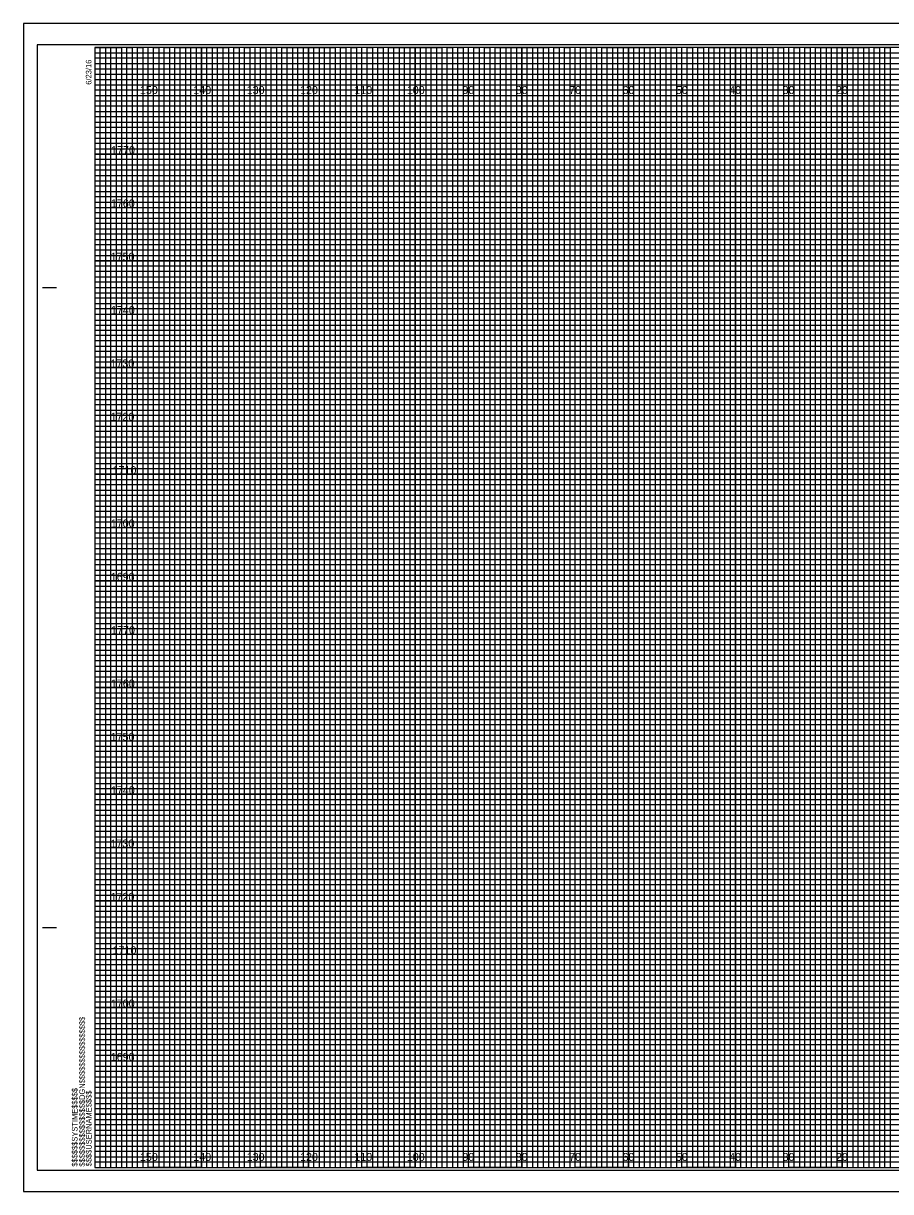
# Model space of a CAD drawing. Extents: x -13 to 1780, y -15 to 3284.
# Drawn here: x 1443.3 to 1605.8, y -14.8 to 204.2 of the extents above; entities that cross this region are included whole.
import ezdxf

# ---------------------------------------------------------------- set-up
doc = ezdxf.new("R2010")
doc.units = 0
for name, color, linetype in [('Prop Retaining Wall', 7, 'Continuous'), ('Prop SS Cut Line', 7, 'Continuous'), ('Prop SS Fill Line', 7, 'Continuous'), ('Prop SS Transition Line', 7, 'Continuous'), ('Prop XS Earthwork Shape', 7, 'Continuous'), ('Prop XS Noise Wall', 7, 'Continuous'), ('Prop XS Station Labels', 7, 'Continuous'), ('Raster_Level_0', 7, 'Continuous'), ('Scratch_Level_3', 7, 'Continuous'), ('Scratch_Level_7', 7, 'Continuous'), ('Typical Bridge Rail CELL', 7, 'Continuous')]:
    doc.layers.add(name, color=color, linetype=linetype)

msp = doc.modelspace()

# ---------------------------------------------------------------- linework, layer by layer
at = {"layer": 'Prop Retaining Wall'}
for p, q in [((1446.88, 154.71), (1449.38, 154.71)), ((1446.98, 154.71), (1449.48, 154.71)), ((1446.88, 34.71), (1449.38, 34.71)), ((1446.98, 34.71), (1449.48, 34.71)), ((1456.68, -10.29), (1456.68, -10.29)), ((1456.68, -10.29), (1456.68, -10.29)), ((1456.68, -10.29), (1456.68, -10.29)), ((1456.68, -10.29), (1456.68, -10.29)), ((1456.68, -10.29), (1456.68, -10.29)), ((1456.68, -10.29), (1456.68, -10.29)), ((1456.68, -10.29), (1456.68, -10.29))]:
    msp.add_line(p, q, dxfattribs=at)
msp.add_lwpolyline([(1776.68, 199.71), (1456.68, 199.71), (1456.68, -10.29), (1776.68, -10.29)], close=True, dxfattribs=at)
at = {"layer": 'Prop SS Cut Line'}
for points in [[(1456.68, 199.71), (1461.68, 199.71), (1461.68, -10.29), (1471.68, -10.29), (1471.68, 199.71), (1481.68, 199.71), (1481.68, -10.29), (1491.68, -10.29), (1491.68, 199.71), (1501.68, 199.71), (1501.68, -10.29), (1511.68, -10.29), (1511.68, 199.71), (1521.68, 199.71), (1521.68, -10.29), (1531.68, -10.29), (1531.68, 199.71), (1541.68, 199.71), (1541.68, -10.29), (1551.68, -10.29), (1551.68, 199.71), (1561.68, 199.71), (1561.68, -10.29), (1571.68, -10.29), (1571.68, 199.71), (1581.68, 199.71), (1581.68, -10.29), (1591.68, -10.29), (1591.68, 199.71), (1601.68, 199.71), (1601.68, -10.29), (1611.68, -10.29)], [(1456.68, 194.71), (1731.68, 194.71)], [(1456.68, 174.71), (1776.68, 174.71), (1776.68, 184.71), (1456.68, 184.71)], [(1456.68, 154.71), (1776.68, 154.71), (1776.68, 164.71), (1456.68, 164.71)], [(1456.68, 134.71), (1776.68, 134.71), (1776.68, 144.71), (1456.68, 144.71)], [(1456.68, 114.71), (1776.68, 114.71), (1776.68, 124.71), (1456.68, 124.71)], [(1456.68, 94.71), (1776.68, 94.71), (1776.68, 104.71), (1456.68, 104.71)], [(1456.68, 74.71), (1776.68, 74.71), (1776.68, 84.71), (1456.68, 84.71)], [(1456.68, 54.71), (1776.68, 54.71), (1776.68, 64.71), (1456.68, 64.71)], [(1456.68, 34.71), (1776.68, 34.71), (1776.68, 44.71), (1456.68, 44.71)], [(1456.68, 14.71), (1776.68, 14.71), (1776.68, 24.71), (1456.68, 24.71)], [(1456.68, -5.29), (1776.68, -5.29), (1776.68, 4.71), (1456.68, 4.71)]]:
    msp.add_lwpolyline(points, dxfattribs=at)
at = {"layer": 'Prop SS Fill Line'}
for p, q in [((1466.68, 199.71), (1456.68, 199.71)), ((1466.68, -10.29), (1466.68, 199.71)), ((1486.68, 199.71), (1476.68, 199.71)), ((1476.68, 199.71), (1476.68, -10.29)), ((1486.68, -10.29), (1486.68, 199.71)), ((1506.68, 199.71), (1496.68, 199.71)), ((1496.68, 199.71), (1496.68, -10.29)), ((1506.68, -10.29), (1506.68, 199.71)), ((1526.68, 199.71), (1516.68, 199.71)), ((1516.68, 199.71), (1516.68, -10.29)), ((1526.68, -10.29), (1526.68, 199.71)), ((1546.68, 199.71), (1536.68, 199.71)), ((1536.68, 199.71), (1536.68, -10.29)), ((1546.68, -10.29), (1546.68, 199.71)), ((1566.68, 199.71), (1556.68, 199.71)), ((1556.68, 199.71), (1556.68, -10.29)), ((1566.68, -10.29), (1566.68, 199.71)), ((1586.68, 199.71), (1576.68, 199.71)), ((1576.68, 199.71), (1576.68, -10.29)), ((1586.68, -10.29), (1586.68, 199.71)), ((1606.68, 199.71), (1596.68, 199.71)), ((1596.68, 199.71), (1596.68, -10.29)), ((1476.68, -10.29), (1466.68, -10.29)), ((1496.68, -10.29), (1486.68, -10.29)), ((1516.68, -10.29), (1506.68, -10.29)), ((1536.68, -10.29), (1526.68, -10.29)), ((1556.68, -10.29), (1546.68, -10.29)), ((1576.68, -10.29), (1566.68, -10.29)), ((1596.68, -10.29), (1586.68, -10.29))]:
    msp.add_line(p, q, dxfattribs=at)
for points in [[(1456.68, 189.71), (1776.68, 189.71), (1776.68, 179.71), (1456.68, 179.71)], [(1456.68, 169.71), (1776.68, 169.71), (1776.68, 159.71), (1456.68, 159.71)], [(1456.68, 149.71), (1776.68, 149.71), (1776.68, 139.71), (1456.68, 139.71)], [(1456.68, 129.71), (1776.68, 129.71), (1776.68, 119.71), (1456.68, 119.71)], [(1456.68, 109.71), (1776.68, 109.71), (1776.68, 99.71), (1456.68, 99.71)], [(1456.68, 89.71), (1776.68, 89.71), (1776.68, 79.71), (1456.68, 79.71)], [(1456.68, 69.71), (1776.68, 69.71), (1776.68, 59.71), (1456.68, 59.71)], [(1456.68, 49.71), (1776.68, 49.71), (1776.68, 39.71), (1456.68, 39.71)], [(1456.68, 29.71), (1776.68, 29.71), (1776.68, 19.71), (1456.68, 19.71)], [(1456.68, 9.71), (1776.68, 9.71), (1776.68, -0.29), (1456.68, -0.29)]]:
    msp.add_lwpolyline(points, dxfattribs=at)
at = {"layer": 'Prop SS Transition Line'}
for p, q in [((1456.68, 198.71), (1716.68, 198.71)), ((1716.68, 197.69), (1456.68, 197.69)), ((1456.68, 197.69), (1456.68, 196.71)), ((1456.68, 196.71), (1716.68, 196.71)), ((1716.68, 195.6), (1456.68, 195.6)), ((1456.68, 195.6), (1456.68, 193.71)), ((1456.68, 193.71), (1776.68, 193.71))]:
    msp.add_line(p, q, dxfattribs=at)
for points in [[(1456.68, 192.71), (1726.68, 192.71), (1776.68, 192.71), (1776.68, 191.71), (1456.68, 191.71)], [(1456.68, 190.71), (1776.68, 190.71), (1776.68, 188.71), (1456.68, 188.71)], [(1456.68, 187.71), (1776.68, 187.71), (1776.68, 186.71), (1456.68, 186.69)], [(1456.68, 185.71), (1776.68, 185.71), (1776.68, 183.71), (1456.68, 183.71)], [(1456.68, 182.71), (1776.68, 182.71), (1776.68, 181.71), (1456.68, 181.71)], [(1456.68, 180.71), (1776.68, 180.71), (1776.68, 178.71), (1456.68, 178.71)], [(1456.68, 177.71), (1776.68, 177.71), (1776.68, 176.71), (1456.68, 176.71)], [(1456.68, 175.71), (1776.68, 175.71), (1776.68, 173.71), (1456.68, 173.71)], [(1456.68, 172.71), (1776.68, 172.71), (1776.68, 171.71), (1456.68, 171.71)], [(1456.68, 170.71), (1776.68, 170.71), (1776.68, 168.71), (1456.68, 168.71)], [(1456.68, 167.71), (1776.68, 167.71), (1776.68, 166.71), (1456.68, 166.71)], [(1456.68, 165.71), (1776.68, 165.71), (1776.68, 163.66), (1776.68, 162.71), (1776.68, 161.71), (1456.68, 161.71)], [(1456.68, 163.71), (1776.68, 163.71), (1776.68, 162.71), (1456.68, 162.71)], [(1456.68, 160.71), (1776.68, 160.71), (1776.68, 158.71), (1456.68, 158.74)], [(1456.68, 158.74), (1776.68, 158.71), (1776.68, 157.71), (1456.68, 157.71)], [(1456.68, 156.71), (1776.68, 156.71), (1776.68, 155.71), (1456.68, 155.71)], [(1456.68, 153.71), (1776.68, 153.71), (1776.68, 152.71), (1456.68, 152.71)], [(1456.68, 151.71), (1776.68, 151.71), (1776.68, 150.71), (1456.68, 150.71)], [(1456.61, 148.6), (1776.68, 148.6), (1776.68, 147.59), (1456.61, 147.59)], [(1456.68, 146.71), (1776.68, 146.71), (1776.68, 145.71), (1456.68, 145.71)], [(1456.68, 143.71), (1776.68, 143.71), (1776.68, 142.71), (1456.68, 142.71)], [(1456.68, 141.71), (1776.68, 141.71), (1776.68, 140.71), (1456.68, 140.71)], [(1456.68, 138.71), (1776.68, 138.71), (1776.68, 137.71), (1456.68, 137.71)], [(1456.68, 136.71), (1776.68, 136.71), (1776.68, 135.71), (1456.68, 135.71)], [(1456.68, 133.71), (1776.68, 133.71), (1776.68, 132.71), (1456.68, 132.71)], [(1456.68, 131.71), (1776.68, 131.71), (1776.68, 130.71), (1456.68, 130.71)], [(1456.68, 128.71), (1776.68, 128.71), (1776.67, 127.69), (1456.68, 127.71)], [(1456.68, 126.71), (1776.68, 126.71), (1776.68, 125.71), (1456.68, 125.71)], [(1456.68, 123.71), (1776.68, 123.71), (1776.68, 122.71), (1456.68, 122.71)], [(1456.68, 121.71), (1776.68, 121.71), (1776.68, 120.71), (1456.68, 120.71)], [(1456.68, 118.71), (1776.68, 118.71), (1776.68, 117.71), (1456.68, 117.71)], [(1456.68, 116.71), (1776.68, 116.71), (1776.68, 115.71), (1456.68, 115.71)], [(1456.68, 113.71), (1776.68, 113.71), (1776.68, 112.71), (1456.68, 112.71)], [(1456.68, 111.71), (1776.68, 111.71), (1776.68, 110.71), (1456.68, 110.71)], [(1456.68, 108.71), (1776.68, 108.71), (1776.68, 107.71), (1456.68, 107.71)], [(1456.68, 106.7), (1776.75, 106.62), (1776.68, 105.71), (1456.68, 105.71)], [(1456.68, 103.71), (1776.68, 103.71), (1776.68, 102.71), (1456.68, 102.71)], [(1456.68, 101.71), (1776.68, 101.71), (1776.68, 100.71), (1456.68, 100.71)], [(1456.68, 98.71), (1776.68, 98.71), (1776.68, 97.71), (1456.68, 97.71)], [(1456.68, 96.71), (1776.68, 96.71), (1776.68, 95.71), (1456.68, 95.71)], [(1456.68, 93.71), (1776.68, 93.71), (1776.68, 92.71), (1456.68, 92.71)], [(1456.68, 91.71), (1776.68, 91.71), (1776.68, 90.71), (1456.68, 90.71)], [(1456.68, 88.71), (1776.68, 88.71), (1776.68, 87.71), (1456.68, 87.71)], [(1456.68, 86.71), (1776.68, 86.71), (1776.68, 85.71), (1456.68, 85.71)], [(1456.68, 83.71), (1776.68, 83.71), (1776.68, 82.71), (1456.68, 82.71)], [(1456.68, 81.71), (1776.68, 81.71), (1776.68, 80.71), (1456.68, 80.71)], [(1456.68, 78.71), (1776.68, 78.71), (1776.68, 77.71), (1456.68, 77.71)], [(1456.68, 76.71), (1776.68, 76.71), (1776.68, 75.71), (1456.68, 75.71)], [(1456.68, 73.71), (1776.68, 73.71), (1776.68, 72.71), (1456.68, 72.71)], [(1456.68, 71.71), (1776.68, 71.71), (1776.68, 70.71), (1456.68, 70.71)], [(1456.68, 68.71), (1776.68, 68.71), (1776.67, 67.69), (1456.68, 67.71)], [(1456.68, 66.71), (1776.68, 66.71), (1776.68, 65.71), (1456.68, 65.71)], [(1456.68, 63.71), (1776.68, 63.71), (1776.68, 62.71), (1456.68, 62.71)], [(1456.68, 61.71), (1776.68, 61.71), (1776.68, 60.71), (1456.68, 60.71)], [(1456.68, 58.71), (1776.68, 58.71), (1776.68, 57.71), (1456.68, 57.71)], [(1456.68, 56.71), (1776.68, 56.71), (1776.68, 55.71), (1456.68, 55.71)], [(1456.68, 53.71), (1776.68, 53.71), (1776.68, 52.71), (1456.68, 52.71)], [(1456.68, 51.71), (1776.68, 51.71), (1776.68, 50.71), (1456.68, 50.71)], [(1456.68, 48.71), (1776.68, 48.71), (1776.68, 47.71), (1456.68, 47.71)], [(1456.68, 46.7), (1776.75, 46.62), (1776.68, 45.71), (1456.68, 45.71)], [(1456.68, 43.71), (1776.68, 43.71), (1776.68, 42.71), (1456.68, 42.71)], [(1456.68, 41.71), (1776.68, 41.71), (1776.68, 40.71), (1456.68, 40.71)], [(1456.68, 38.71), (1776.68, 38.71), (1776.68, 37.71), (1456.68, 37.71)], [(1456.68, 36.71), (1776.68, 36.71), (1776.68, 35.71), (1456.68, 35.71)], [(1456.68, 33.71), (1776.68, 33.71), (1776.68, 32.71), (1456.68, 32.71)], [(1456.68, 31.71), (1776.68, 31.71), (1776.68, 30.71), (1456.68, 30.71)], [(1456.68, 28.71), (1776.68, 28.71), (1776.68, 27.71), (1456.68, 27.71)], [(1456.68, 26.71), (1776.68, 26.71), (1776.68, 25.71), (1456.68, 25.71)], [(1456.68, 23.71), (1776.68, 23.71), (1776.68, 22.71), (1456.68, 22.71)], [(1456.68, 21.71), (1776.68, 21.71), (1776.68, 20.71), (1456.68, 20.71)], [(1456.68, 18.71), (1776.68, 18.71), (1776.68, 17.71), (1456.68, 17.71)], [(1456.68, 16.71), (1776.68, 16.71), (1776.68, 15.71), (1456.68, 15.71)], [(1456.68, 13.71), (1776.68, 13.71), (1776.68, 12.71), (1456.68, 12.71)], [(1456.68, 11.71), (1776.68, 11.71), (1776.68, 10.71), (1456.68, 10.71)], [(1456.68, 8.71), (1776.68, 8.71), (1776.68, 7.71), (1456.68, 7.71)], [(1456.68, 6.71), (1776.68, 6.71), (1776.68, 5.71), (1456.68, 5.71)], [(1456.68, 3.71), (1776.68, 3.71), (1776.68, 2.71), (1456.68, 2.71)], [(1456.68, 1.71), (1776.68, 1.71), (1776.68, 0.71), (1456.68, 0.71)], [(1456.68, -1.29), (1776.68, -1.29), (1776.68, -2.29), (1456.68, -2.29)], [(1456.68, -3.29), (1776.68, -3.29), (1776.68, -4.29), (1456.68, -4.29)], [(1456.68, -6.29), (1776.68, -6.29), (1776.68, -7.29), (1456.68, -7.29)], [(1456.68, -8.29), (1776.68, -8.29), (1776.68, -9.29), (1456.68, -9.29)]]:
    msp.add_lwpolyline(points, dxfattribs=at)
at = {"layer": 'Prop XS Earthwork Shape'}
msp.add_lwpolyline([(1443.28, -14.79), (1779.98, -14.79), (1779.98, 204.21), (1443.28, 204.21)], close=True, dxfattribs=at)
at = {"layer": 'Prop XS Noise Wall'}
for p, q in [((1466.68, -10.29), (1466.68, 199.71)), ((1476.68, -10.29), (1476.68, 199.71)), ((1486.68, -10.29), (1486.68, 199.71)), ((1496.68, -10.29), (1496.68, 199.71)), ((1506.68, -10.29), (1506.68, 199.71)), ((1516.68, -10.29), (1516.68, 199.71)), ((1526.68, -10.29), (1526.68, 199.71)), ((1536.68, -10.29), (1536.68, 199.71)), ((1546.68, -10.29), (1546.68, 199.71)), ((1556.68, -10.29), (1556.68, 199.71)), ((1566.68, -10.29), (1566.68, 199.71)), ((1576.68, -10.29), (1576.68, 199.71)), ((1586.68, -10.29), (1586.68, 199.71)), ((1596.68, -10.29), (1596.68, 199.71)), ((1456.68, 189.71), (1776.68, 189.71)), ((1456.68, 179.71), (1776.68, 179.71)), ((1456.68, 169.71), (1776.68, 169.71)), ((1456.68, 159.71), (1776.68, 159.71)), ((1456.68, 149.71), (1776.68, 149.71)), ((1456.68, 139.71), (1776.68, 139.71)), ((1456.68, 129.71), (1776.68, 129.71)), ((1456.68, 119.71), (1776.68, 119.71)), ((1456.68, 109.71), (1776.68, 109.71)), ((1456.68, 99.71), (1776.68, 99.71)), ((1456.68, 89.71), (1776.68, 89.71)), ((1456.68, 79.71), (1776.68, 79.71)), ((1456.68, 69.71), (1776.68, 69.71)), ((1456.68, 59.71), (1776.68, 59.71)), ((1456.68, 49.71), (1776.68, 49.71)), ((1456.68, 39.71), (1776.68, 39.71)), ((1456.68, 29.71), (1776.68, 29.71)), ((1456.68, 19.71), (1776.68, 19.71)), ((1456.68, 9.71), (1776.68, 9.71)), ((1456.68, -0.29), (1776.68, -0.29))]:
    msp.add_line(p, q, dxfattribs=at)
at = {"layer": 'Prop XS Station Labels'}
for p, q in [((1779.98, 204.21), (1443.28, 204.21)), ((1443.28, 204.21), (1443.28, -14.79)), ((1443.28, -14.79), (1779.98, -14.79))]:
    msp.add_line(p, q, dxfattribs=at)
at = {"layer": 'Scratch_Level_7'}
msp.add_lwpolyline([(1445.88, -10.79), (1779.08, -10.79), (1779.08, 200.21), (1445.88, 200.21)], close=True, dxfattribs=at)
at = {"layer": 'Typical Bridge Rail CELL'}
for points in [[(1456.68, -10.29), (1457.68, -10.29), (1457.68, 199.71), (1458.68, 199.71), (1458.68, -10.29)], [(1458.68, -10.29), (1459.68, -10.29), (1459.68, 199.71), (1460.68, 199.71), (1460.68, -10.29)], [(1461.68, -10.29), (1462.68, -10.29), (1462.68, 199.71), (1463.68, 199.71), (1463.68, -10.29)], [(1463.68, -10.29), (1464.68, -10.29), (1464.68, 199.71), (1465.68, 199.71), (1465.68, -10.29)], [(1466.68, -10.29), (1467.68, -10.29), (1467.68, 199.71), (1468.68, 199.71), (1468.68, -10.29)], [(1468.68, -10.29), (1469.68, -10.29), (1469.68, 199.71), (1470.68, 199.71), (1470.68, -10.29)], [(1471.68, -10.29), (1472.68, -10.29), (1472.68, 199.71), (1473.68, 199.71), (1473.68, -10.29)], [(1473.68, -10.29), (1474.68, -10.29), (1474.68, 199.71), (1475.68, 199.71), (1475.68, -10.29)], [(1476.68, -10.29), (1477.68, -10.29), (1477.68, 199.71), (1478.68, 199.71), (1478.68, -10.29)], [(1478.68, -10.29), (1479.68, -10.29), (1479.68, 199.71), (1480.68, 199.71), (1480.68, -10.29)], [(1481.68, -10.29), (1482.68, -10.29), (1482.68, 199.71), (1483.68, 199.71), (1483.68, -10.29)], [(1483.68, -10.29), (1484.68, -10.29), (1484.68, 199.71), (1485.68, 199.71), (1485.68, -10.29)], [(1486.68, -10.29), (1487.68, -10.29), (1487.68, 199.71), (1488.68, 199.71), (1488.68, -10.29)], [(1488.68, -10.29), (1489.68, -10.29), (1489.68, 199.71), (1490.68, 199.71), (1490.68, -10.29)], [(1491.68, -10.29), (1492.68, -10.29), (1492.68, 199.71), (1493.68, 199.71), (1493.68, -10.29)], [(1493.68, -10.29), (1494.68, -10.29), (1494.68, 199.71), (1495.68, 199.71), (1495.68, -10.29)], [(1496.68, -10.29), (1497.68, -10.29), (1497.68, 199.71), (1498.68, 199.71), (1498.68, -10.29)], [(1498.68, -10.29), (1499.68, -10.29), (1499.68, 199.71), (1500.68, 199.71), (1500.68, -10.29)], [(1501.68, -10.29), (1502.68, -10.29), (1502.68, 199.71), (1503.68, 199.71), (1503.68, -10.29)], [(1503.68, -10.29), (1504.68, -10.29), (1504.68, 199.71), (1505.68, 199.71), (1505.68, -10.29)], [(1506.68, -10.29), (1507.68, -10.29), (1507.68, 199.71), (1508.68, 199.71), (1508.68, -10.29)], [(1508.68, -10.29), (1509.68, -10.29), (1509.68, 199.71), (1510.68, 199.71), (1510.68, -10.29)], [(1511.68, -10.29), (1512.68, -10.29), (1512.68, 199.71), (1513.68, 199.71), (1513.68, -10.29)], [(1513.68, -10.29), (1514.68, -10.29), (1514.68, 199.71), (1515.68, 199.71), (1515.68, -10.29)], [(1516.68, -10.29), (1517.68, -10.29), (1517.68, 199.71), (1518.68, 199.71), (1518.68, -10.29)], [(1518.68, -10.29), (1519.68, -10.29), (1519.68, 199.71), (1520.68, 199.71), (1520.68, -10.29)], [(1521.68, -10.29), (1522.68, -10.29), (1522.68, 199.71), (1523.68, 199.71), (1523.68, -10.29)], [(1523.68, -10.29), (1524.68, -10.29), (1524.68, 199.71), (1525.68, 199.71), (1525.68, -10.29)], [(1526.68, -10.29), (1527.68, -10.29), (1527.68, 199.71), (1528.68, 199.71), (1528.68, -10.29)], [(1528.68, -10.29), (1529.68, -10.29), (1529.68, 199.71), (1530.68, 199.71), (1530.68, -10.29)], [(1531.68, -10.29), (1532.68, -10.29), (1532.68, 199.71), (1533.68, 199.71), (1533.68, -10.29)], [(1533.68, -10.29), (1534.68, -10.29), (1534.68, 199.71), (1535.68, 199.71), (1535.68, -10.29)], [(1536.68, -10.29), (1537.68, -10.29), (1537.68, 199.71), (1538.68, 199.71), (1538.68, -10.29)], [(1538.68, -10.29), (1539.68, -10.29), (1539.68, 199.71), (1540.68, 199.71), (1540.68, -10.29)], [(1541.68, -10.29), (1542.68, -10.29), (1542.68, 199.71), (1543.68, 199.71), (1543.68, -10.29)], [(1543.68, -10.29), (1544.68, -10.29), (1544.68, 199.71), (1545.68, 199.71), (1545.68, -10.29)], [(1546.68, -10.29), (1547.68, -10.29), (1547.68, 199.71), (1548.68, 199.71), (1548.68, -10.29)], [(1548.68, -10.29), (1549.68, -10.29), (1549.68, 199.71), (1550.68, 199.71), (1550.68, -10.29)], [(1551.68, -10.29), (1552.68, -10.29), (1552.68, 199.71), (1553.68, 199.71), (1553.68, -10.29)], [(1553.68, -10.29), (1554.68, -10.29), (1554.68, 199.71), (1555.68, 199.71), (1555.68, -10.29)], [(1556.68, -10.29), (1557.68, -10.29), (1557.68, 199.71), (1558.68, 199.71), (1558.68, -10.29)], [(1558.68, -10.29), (1559.68, -10.29), (1559.68, 199.71), (1560.68, 199.71), (1560.68, -10.29)], [(1561.68, -10.29), (1562.68, -10.29), (1562.68, 199.71), (1563.68, 199.71), (1563.68, -10.29)], [(1563.68, -10.29), (1564.68, -10.29), (1564.68, 199.71), (1565.68, 199.71), (1565.68, -10.29)], [(1566.68, -10.29), (1567.68, -10.29), (1567.68, 199.71), (1568.68, 199.71), (1568.68, -10.29)], [(1568.68, -10.29), (1569.68, -10.29), (1569.68, 199.71), (1570.68, 199.71), (1570.68, -10.29)], [(1571.68, -10.29), (1572.68, -10.29), (1572.68, 199.71), (1573.68, 199.71), (1573.68, -10.29)], [(1573.68, -10.29), (1574.68, -10.29), (1574.68, 199.71), (1575.68, 199.71), (1575.68, -10.29)], [(1576.68, -10.29), (1577.68, -10.29), (1577.68, 199.71), (1578.68, 199.71), (1578.68, -10.29)], [(1578.68, -10.29), (1579.68, -10.29), (1579.68, 199.71), (1580.68, 199.71), (1580.68, -10.29)], [(1581.68, -10.29), (1582.68, -10.29), (1582.68, 199.71), (1583.68, 199.71), (1583.68, -10.29)], [(1583.68, -10.29), (1584.68, -10.29), (1584.68, 199.71), (1585.68, 199.71), (1585.68, -10.29)], [(1586.68, -10.29), (1587.68, -10.29), (1587.68, 199.71), (1588.68, 199.71), (1588.68, -10.29)], [(1588.68, -10.29), (1589.68, -10.29), (1589.68, 199.71), (1590.68, 199.71), (1590.68, -10.29)], [(1591.68, -10.29), (1592.68, -10.29), (1592.68, 199.71), (1593.68, 199.71), (1593.68, -10.29)], [(1593.68, -10.29), (1594.68, -10.29), (1594.68, 199.71), (1595.68, 199.71), (1595.68, -10.29)], [(1596.68, -10.29), (1597.68, -10.29), (1597.68, 199.71), (1598.68, 199.71), (1598.68, -10.29)], [(1598.68, -10.29), (1599.68, -10.29), (1599.68, 199.71), (1600.68, 199.71), (1600.68, -10.29)], [(1601.68, -10.29), (1602.68, -10.29), (1602.68, 199.71), (1603.68, 199.71), (1603.68, -10.29)], [(1603.68, -10.29), (1604.68, -10.29), (1604.68, 199.71), (1605.68, 199.71), (1605.68, -10.29)]]:
    msp.add_lwpolyline(points, dxfattribs=at)

# ---------------------------------------------------------------- texts
at = {"layer": 'Prop Retaining Wall'}
for s, p in [('6/23/16', (1456.03, 192.71)), ('$$$$$$$$$$$$$$$$DGN$$$$$$$$$$$$$$$$', (1454.8, -10.11)), ('$$$$$$SYSTIME$$$$$', (1453.42, -10.11)), ('$$$$USERNAME$$$$', (1456.06, -10.06))]:
    msp.add_text(s, height=1.05, rotation=90, dxfattribs=at).set_placement(p)
at = {"layer": 'Raster_Level_0'}
for s, p in [('150', (1465.12, 190.96)), ('140', (1475.12, 190.96)), ('130', (1485.12, 190.96)), ('120', (1495.12, 190.96)), ('110', (1505.3, 190.96)), ('100', (1515.12, 190.96)), ('90', (1525.53, 190.96)), ('80', (1535.53, 190.96)), ('70', (1545.53, 190.96)), ('60', (1555.53, 190.96)), ('50', (1565.53, 190.96)), ('40', (1575.53, 190.96)), ('30', (1585.53, 190.96)), ('20', (1595.53, 190.96)), ('150', (1465.12, -9.04)), ('140', (1475.12, -9.04)), ('130', (1485.12, -9.04)), ('120', (1495.12, -9.04)), ('110', (1505.3, -9.04)), ('100', (1515.12, -9.04)), ('90', (1525.53, -9.04)), ('80', (1535.53, -9.04)), ('70', (1545.53, -9.04)), ('60', (1555.53, -9.04)), ('50', (1565.53, -9.04)), ('40', (1575.53, -9.04)), ('30', (1585.53, -9.04)), ('20', (1595.53, -9.04))]:
    msp.add_text(s, height=1.5, dxfattribs=at).set_placement(p)
at = {"layer": 'Scratch_Level_3'}
for s, p in [('1770', (1459.72, 179.71)), ('1760', (1459.68, 169.71)), ('1750', (1459.63, 159.71)), ('1740', (1459.68, 149.71)), ('1730', (1459.6, 139.71)), ('1720', (1459.61, 129.71)), ('1710', (1459.99, 119.71)), ('1700', (1459.66, 109.71)), ('1690', (1459.65, 99.71)), ('1770', (1459.72, 89.71)), ('1760', (1459.68, 79.71)), ('1750', (1459.63, 69.71)), ('1740', (1459.68, 59.71)), ('1730', (1459.6, 49.71)), ('1720', (1459.61, 39.71)), ('1710', (1459.99, 29.71)), ('1700', (1459.66, 19.71)), ('1690', (1459.65, 9.71))]:
    msp.add_text(s, height=1.5, dxfattribs=at).set_placement(p)

doc.saveas('drawing.dxf')
